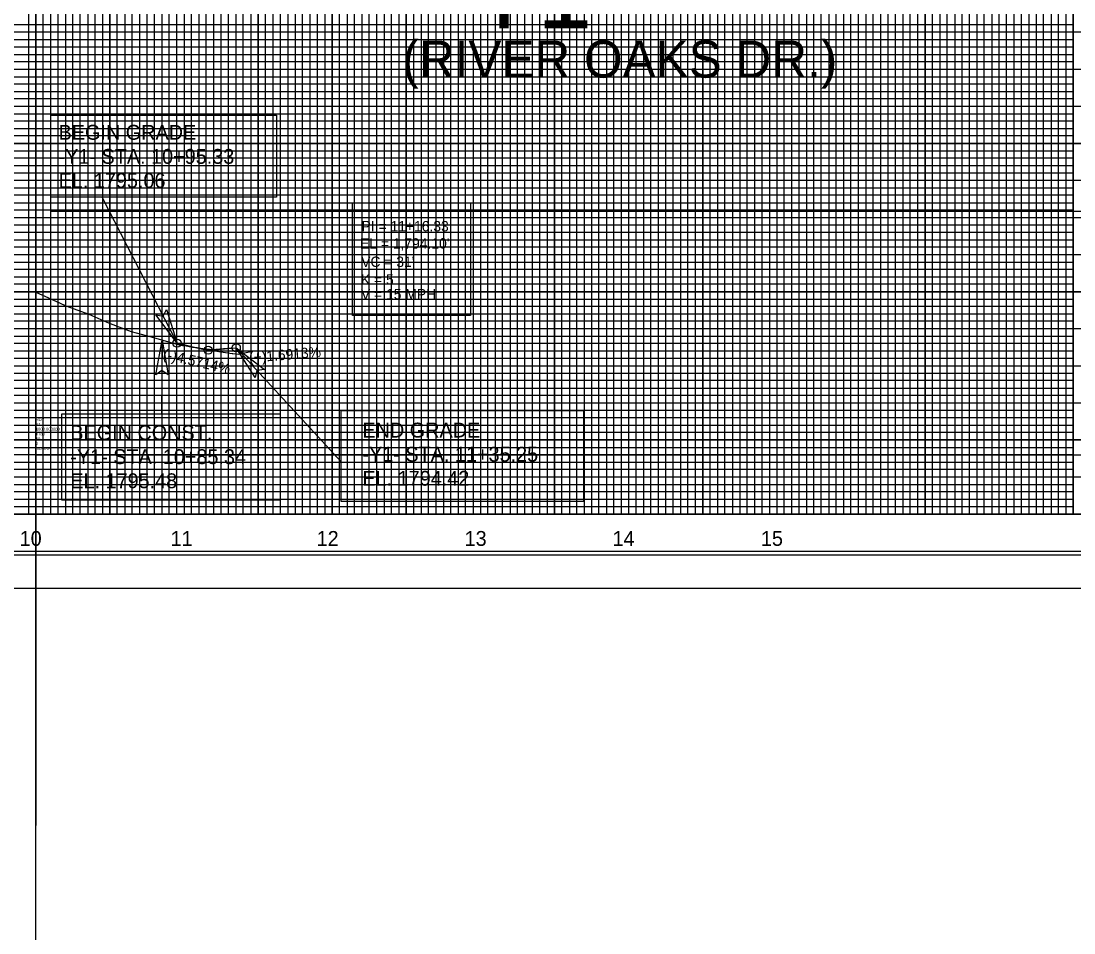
# Model space of a CAD drawing. Extents: x 572269 to 579912, y -56875 to -49627.
# Drawn here: x 574575 to 575285, y -54080 to -53465 of the extents above; entities that cross this region are included whole.
import ezdxf

# ---------------------------------------------------------------- set-up
doc = ezdxf.new("R2010")
doc.units = 0
for name, color, linetype in [('Exist Profile Cell', 7, 'Continuous'), ('Exist Vertical Profile Ground Line', 7, 'Continuous'), ('Exist Vertical Profile Horizontal Axis Label Major', 7, 'Continuous'), ('Prop Grid Mask', 7, 'Continuous'), ('Prop PFL Text', 7, 'Continuous'), ('Prop Vertical Profile Curve Label', 7, 'Continuous'), ('Prop Vertical Profile Grade', 7, 'Continuous'), ('Prop Vertical Profile Grade Label', 7, 'Continuous'), ('Prop VPI Label', 7, 'Continuous'), ('Scratch_Level_0', 7, 'Continuous'), ('Scratch_Level_3', 7, 'Continuous'), ('Scratch_Level_5', 7, 'Continuous'), ('Scratch_Level_6', 7, 'Continuous'), ('Sheet Cutting Line CELL', 7, 'Continuous'), ('Sheet DOT Grid CELL', 7, 'Continuous'), ('Sheet Layout Profile Border', 7, 'Continuous'), ('Sheet Plot Border Inside CELL', 7, 'Continuous'), ('Sheet Plot Border Outside CELL', 7, 'Continuous'), ('Sheet Profile CELL', 7, 'Continuous'), ('Sheet Profile Grid Major CELL', 7, 'Continuous'), ('Sheet Profile Grid Middle CELL', 7, 'Continuous'), ('Sheet Profile Grid Minor CELL', 7, 'Continuous'), ('Typical Terminator CELL', 7, 'Continuous')]:
    doc.layers.add(name, color=color, linetype=linetype)

# ---------------------------------------------------------------- blocks, each defined once
blk = doc.blocks.new('TERMINATOR')
at = {"layer": 'Typical Terminator CELL'}
blk.add_lwpolyline([(-0.469, 0.081), (0, 0), (-0.471, -0.083), (-0.411, 0)], close=True, dxfattribs=at)
blk = doc.blocks.new('PROFILE SHEET SINGLE')
at = {"layer": 'Sheet Cutting Line CELL'}
blk.add_line((-3.34, -0.5), (30.34, -0.5), dxfattribs=at)
at = {"layer": 'Sheet DOT Grid CELL'}
for p, q in [((15, 21), (15, 0.5)), ((16, 21), (16, 0.5)), ((17, 21), (17, 0.5)), ((18, 21), (18, 0.5)), ((19, 21), (19, 0.5)), ((20, 21), (20, 0.5)), ((21, 21), (21, 0.5)), ((22, 21), (22, 0.5)), ((23, 21), (23, 0.5)), ((24, 21), (24, 0.5)), ((25, 21), (25, 0.5)), ((26, 0.5), (26, 18.249)), ((27, 0.5), (27, 18.249)), ((28, 0.5), (28, 18.249)), ((29, 0.5), (29, 18.249)), ((0, 6.5), (30, 6.5)), ((0, 5.5), (30, 5.5)), ((0, 4.5), (30, 4.5)), ((0, 3.5), (30, 3.5)), ((0, 2.5), (30, 2.5)), ((0, 1.5), (30, 1.5))]:
    blk.add_line(p, q, dxfattribs=at)
at = {"layer": 'Sheet Plot Border Inside CELL'}
blk.add_lwpolyline([(30.25, 21.051), (-3.08, 21.051), (-3.08, -0.051), (30.25, -0.051)], close=True, dxfattribs=at)
at = {"layer": 'Sheet Plot Border Outside CELL'}
blk.add_lwpolyline([(30.34, 21.5), (-3.34, 21.5), (-3.34, -0.5), (30.34, -0.5)], close=True, dxfattribs=at)
at = {"layer": 'Sheet Profile CELL'}
blk.add_line((30, 0.5), (0, 0.5), dxfattribs=at)
blk.add_lwpolyline([(30, 21), (0, 21), (0, 0), (30, 0)], close=True, dxfattribs=at)
at = {"layer": 'Sheet Profile Grid Major CELL'}
for points in [[(15, 21), (15, 0.5), (16, 0.5), (16, 21)], [(17, 21), (17, 0.5), (18, 0.5), (18, 21)], [(19, 21), (19, 0.5), (20, 0.5), (20, 21)], [(21, 21), (21, 0.5), (22, 0.5), (22, 21)], [(23, 21), (23, 0.5), (24, 0.5), (24, 21)], [(25, 21), (25, 0.5), (26, 0.5), (26, 21)], [(27, 18.249), (27, 0.5), (28, 0.5), (28, 18.249)], [(29, 18.249), (29, 0.5), (30, 0.5)], [(30, 5.5), (0, 5.5), (0, 6.5), (30, 6.5)], [(30, 3.5), (0, 3.5), (0, 4.5), (30, 4.5)], [(30, 1.5), (0, 1.5), (0, 2.5), (30, 2.5)]]:
    blk.add_lwpolyline(points, dxfattribs=at)
at = {"layer": 'Sheet Profile Grid Middle CELL'}
for points in [[(14.5, 21), (14.5, 0.5), (15.5, 0.5), (15.5, 21)], [(16.5, 21), (16.5, 0.5), (17.5, 0.5), (17.5, 21)], [(18.5, 21), (18.5, 0.5), (19.5, 0.5), (19.5, 21)], [(20.5, 21), (20.5, 0.5), (21.5, 0.5), (21.5, 21)], [(22.5, 21), (22.5, 0.5), (23.5, 0.5), (23.5, 21)], [(24.5, 21), (24.5, 0.5), (25.5, 0.5), (25.5, 21)], [(26.5, 18.249), (26.5, 0.5), (27.5, 0.5), (27.5, 18.249)], [(28.5, 18.249), (28.5, 0.5)], [(30, 7), (0, 7), (0, 6), (30, 6)], [(30, 5), (0, 5), (0, 4), (30, 4)], [(30, 3), (0, 3), (0, 2), (30, 2)], [(30, 1), (0, 1)]]:
    blk.add_lwpolyline(points, dxfattribs=at)
at = {"layer": 'Sheet Profile Grid Minor CELL'}
for points in [[(14.9, 21), (14.9, 0.5), (15.1, 0.5), (15.1, 21)], [(15.2, 21), (15.2, 0.5)], [(15.2, 0.5), (15.3, 0.5), (15.3, 20.988)], [(15.4, 20.988), (15.4, 0.5), (15.6, 0.5), (15.6, 21)], [(15.7, 21), (15.7, 0.5), (15.8, 0.5), (15.8, 21)], [(15.9, 21), (15.9, 0.5), (16.1, 0.5), (16.1, 21)], [(16.2, 21), (16.2, 0.5), (16.3, 0.5), (16.3, 21)], [(16.4, 21), (16.4, 0.5), (16.6, 0.5), (16.6, 21)], [(16.7, 21), (16.7, 0.5), (16.8, 0.5), (16.8, 21)], [(16.9, 21), (16.9, 0.5), (17.1, 0.5), (17.1, 21)], [(17.2, 21), (17.2, 0.5), (17.3, 0.5), (17.3, 21)], [(17.4, 21), (17.4, 0.5), (17.6, 0.5), (17.6, 21)], [(17.7, 21), (17.7, 0.5), (17.8, 0.5), (17.8, 21)], [(17.9, 21), (17.9, 0.5), (18.1, 0.5), (18.1, 21)], [(18.2, 21), (18.2, 0.5), (18.3, 0.5), (18.3, 21)], [(18.4, 21), (18.4, 0.5), (18.6, 0.5), (18.6, 21)], [(18.7, 21), (18.7, 0.5), (18.8, 0.5), (18.8, 21)], [(18.9, 21), (18.9, 0.5), (19.1, 0.5), (19.1, 21)], [(19.2, 21), (19.2, 0.5), (19.3, 0.5), (19.3, 21)], [(19.4, 21), (19.4, 0.5), (19.6, 0.5), (19.6, 21)], [(19.7, 21), (19.7, 0.5), (19.8, 0.5), (19.8, 21)], [(19.9, 21), (19.9, 0.5), (20.1, 0.5), (20.1, 21)], [(20.2, 21), (20.2, 0.5), (20.3, 0.5), (20.3, 21)], [(20.4, 21), (20.4, 0.5), (20.6, 0.5), (20.6, 21)], [(20.7, 21), (20.7, 0.5), (20.8, 0.5), (20.8, 21)], [(20.9, 21), (20.9, 0.5), (21.1, 0.5), (21.1, 21)], [(21.2, 21), (21.2, 0.5), (21.3, 0.5), (21.3, 21)], [(21.4, 21), (21.4, 0.5)], [(21.4, 0.5), (21.6, 0.5), (21.6, 21)], [(21.7, 21), (21.7, 0.5), (21.8, 0.5), (21.8, 21)], [(21.9, 21), (21.9, 0.5), (22.1, 0.5), (22.1, 21)], [(22.2, 21), (22.2, 0.5), (22.3, 0.5), (22.3, 21)], [(22.4, 21), (22.4, 0.5), (22.6, 0.5), (22.6, 21)], [(22.7, 21), (22.7, 0.5), (22.8, 0.5), (22.8, 21)], [(22.9, 21), (22.9, 0.5), (23.1, 0.5), (23.1, 21)], [(23.2, 21), (23.2, 0.5), (23.3, 0.5), (23.3, 21)], [(23.4, 21), (23.4, 0.5), (23.6, 0.5), (23.6, 21)], [(23.7, 21), (23.7, 0.5), (23.8, 0.5), (23.8, 21)], [(23.9, 21), (23.9, 0.5), (24.1, 0.5), (24.1, 21)], [(24.2, 21), (24.2, 0.5), (24.3, 0.5), (24.3, 21)], [(24.4, 21), (24.4, 0.5), (24.6, 0.5), (24.6, 21)], [(24.7, 21), (24.7, 0.5), (24.8, 0.5), (24.8, 21)], [(24.9, 21), (24.9, 0.5), (25.1, 0.5), (25.1, 21)], [(25.2, 21), (25.2, 0.5), (25.3, 0.5), (25.3, 21)], [(25.4, 21), (25.4, 0.5), (25.6, 0.5), (25.6, 21)], [(25.7, 21), (25.7, 0.5), (25.8, 0.5), (25.8, 21)], [(25.9, 21), (25.9, 0.5), (26.1, 0.5), (26.1, 18.249)], [(26.2, 18.249), (26.2, 0.5), (26.3, 0.5), (26.3, 18.249)], [(26.4, 18.249), (26.4, 0.5), (26.6, 0.5), (26.6, 18.249)], [(26.7, 18.249), (26.7, 0.5), (26.8, 0.5), (26.8, 18.249)], [(26.9, 18.249), (26.9, 0.5), (27.1, 0.5), (27.1, 18.249)], [(27.2, 18.249), (27.2, 0.5), (27.3, 0.5), (27.3, 18.249)], [(27.4, 18.249), (27.4, 0.5), (27.6, 0.5), (27.6, 18.249)], [(27.7, 18.249), (27.7, 0.5)], [(27.7, 0.5), (27.8, 0.5), (27.8, 18.249)], [(27.9, 18.249), (27.9, 0.5), (28.1, 0.5), (28.1, 18.249)], [(28.2, 18.249), (28.2, 0.5), (28.3, 0.5), (28.3, 18.249)], [(28.4, 18.249), (28.4, 0.5), (28.6, 0.5), (28.6, 18.249)], [(28.7, 18.249), (28.7, 0.5), (28.8, 0.5), (28.8, 18.249)], [(28.9, 18.249), (28.9, 0.5), (29.1, 0.5)], [(29, 7.1), (1, 7.1), (1, 6.9), (29, 6.9)], [(29, 6.8), (1, 6.8), (1, 6.7), (29, 6.7)], [(29, 6.6), (1, 6.6), (1, 6.4), (29, 6.4)], [(29, 6.3), (1, 6.3), (1, 6.2), (29, 6.2)], [(29, 6.1), (1, 6.1), (1, 5.9), (29, 5.9)], [(29, 5.8), (1, 5.8), (1, 5.7), (29, 5.7)], [(29, 5.6), (1, 5.6), (1, 5.4), (29, 5.4)], [(29, 5.3), (1, 5.3), (1, 5.2), (29, 5.2)], [(29, 5.1), (1, 5.1), (1, 4.9), (29, 4.9)], [(29, 4.8), (1, 4.8), (1, 4.7), (29, 4.7)], [(29, 4.6), (1, 4.6)], [(1, 4.4), (29, 4.4)], [(29, 4.3), (1, 4.3), (1, 4.2), (29, 4.2)], [(29, 4.1), (1, 4.1)], [(1, 3.9), (29, 3.9)], [(29, 3.8), (1, 3.8), (1, 3.7), (29, 3.7)], [(29, 3.6), (1, 3.6), (1, 3.4), (29, 3.4)], [(29, 3.3), (1, 3.3), (1, 3.2), (29, 3.2)], [(29, 3.1), (1, 3.1), (1, 2.9), (29, 2.9)], [(29, 2.8), (1, 2.8), (1, 2.7), (29, 2.7)], [(29, 2.6), (1, 2.6), (1, 2.4), (29, 2.4)], [(29, 2.3), (1, 2.3), (1, 2.2), (29, 2.2)], [(29, 2.1), (1, 2.1), (1, 1.9), (29, 1.9)], [(29, 1.8), (1, 1.8), (1, 1.7), (29, 1.7)], [(29, 1.6), (1, 1.6), (1, 1.4), (29, 1.4)], [(29, 1.3), (1, 1.3), (1, 1.2), (29, 1.2)], [(29, 1.1), (1, 1.1), (1, 0.9), (29, 0.9)], [(29, 0.8), (1, 0.8), (1, 0.7), (29, 0.7)], [(29, 0.6), (1, 0.6)]]:
    blk.add_lwpolyline(points, dxfattribs=at)

msp = doc.modelspace()

# ---------------------------------------------------------------- linework, layer by layer
at = {"layer": 'Exist Profile Cell'}
for p, q in [((574584.69, -53347.71), (574584.69, -53597.71)), ((574584.69, -53757.71), (574584.69, -53507.71)), ((574584.69, -53757.71), (574730.02, -53757.71)), ((574584.69, -53757.71), (574584.69, -54007.71))]:
    msp.add_line(p, q, dxfattribs=at)
at = {"layer": 'Exist Vertical Profile Ground Line'}
msp.add_lwpolyline([(574584.69, -53648.13), (574593.15, -53651.84), (574604.1, -53656.84), (574604.67, -53657.04), (574605, -53657.16), (574620.5, -53662.83), (574632.57, -53668.34), (574640.73, -53671.39), (574649.01, -53674.48), (574662.56, -53678.26), (574674.24, -53681.49), (574680.76, -53683.32), (574681.67, -53683.5), (574683.73, -53683.91), (574686.09, -53684.27), (574688.09, -53684.69), (574690.47, -53685.04), (574692.42, -53685.46), (574694.49, -53685.76), (574696.35, -53686.18), (574717.22, -53689.31), (574717.63, -53689.39), (574721.14, -53689.89), (574728.95, -53688.3), (574730.02, -53688.06)], dxfattribs=at)
at = {"layer": 'Prop Grid Mask'}
for points in [[(574594.87, -53528.64), (574747.2, -53528.64), (574747.2, -53584.06), (574594.87, -53584.06)], [(574798.45, -53587.76), (574877.97, -53587.76), (574877.97, -53663.89), (574798.45, -53663.89)], [(574790.65, -53727.9), (574954.27, -53727.9), (574954.27, -53789.22), (574790.65, -53789.22)], [(574602.21, -53730.1), (574749.66, -53730.1), (574749.66, -53788.38), (574602.21, -53788.38)]]:
    msp.add_lwpolyline(points, close=True, dxfattribs=at)
at = {"layer": 'Prop PFL Text'}
for p, q in [((574680.02, -53682.41), (574629.57, -53584.06)), ((574670.03, -53680.31), (574669.52, -53730.1)), ((574719.94, -53685.61), (574790.65, -53762.55))]:
    msp.add_line(p, q, dxfattribs=at)
at = {"layer": 'Prop Vertical Profile Grade'}
for p, q in [((574680.02, -53682.41), (574692.51, -53685.26)), ((574680.02, -53682.41), (574685.52, -53683.67)), ((574709.52, -53686.49), (574719.94, -53685.61)), ((574716.52, -53685.9), (574719.94, -53685.61))]:
    msp.add_line(p, q, dxfattribs=at)
msp.add_spline([(574692.51, -53685.26), (574692.85, -53685.34), (574693.19, -53685.42), (574693.53, -53685.49), (574693.87, -53685.56), (574694.21, -53685.63), (574694.55, -53685.69), (574694.89, -53685.76), (574695.23, -53685.82), (574695.57, -53685.88), (574695.91, -53685.94), (574696.25, -53685.99), (574696.59, -53686.04), (574696.93, -53686.09), (574697.27, -53686.14), (574697.61, -53686.19), (574697.95, -53686.24), (574698.3, -53686.28), (574698.64, -53686.32), (574698.98, -53686.36), (574699.32, -53686.39), (574699.66, -53686.43), (574700, -53686.46), (574700.34, -53686.49), (574700.68, -53686.52), (574701.02, -53686.54), (574701.36, -53686.57), (574701.7, -53686.59), (574702.04, -53686.61), (574702.38, -53686.62), (574702.72, -53686.64), (574703.06, -53686.65), (574703.4, -53686.66), (574703.74, -53686.67), (574704.08, -53686.68), (574704.42, -53686.68), (574704.76, -53686.68), (574705.1, -53686.68), (574705.44, -53686.68), (574705.78, -53686.68), (574706.12, -53686.67), (574706.46, -53686.66), (574706.8, -53686.65), (574707.14, -53686.64), (574707.48, -53686.62), (574707.82, -53686.61), (574708.16, -53686.59), (574708.5, -53686.57), (574708.84, -53686.54), (574709.18, -53686.52), (574709.52, -53686.49)], degree=3, dxfattribs=at)
at = {"layer": 'Prop VPI Label'}
for p, q in [((574685.52, -53683.67), (574698.34, -53686.6)), ((574692.51, -53685.26), (574698.34, -53686.6)), ((574716.52, -53685.9), (574703.76, -53686.98)), ((574709.52, -53686.49), (574703.76, -53686.98))]:
    msp.add_line(p, q, dxfattribs=at)
for centre in [(574680.02, -53682.41), (574680.02, -53682.41), (574701.02, -53687.21), (574701.02, -53687.21), (574719.94, -53685.61), (574719.94, -53685.61)]:
    msp.add_circle(centre, 2.75, dxfattribs=at)
at = {"layer": 'Scratch_Level_0'}
msp.add_line((573884.69, -53497.71), (575215.07, -53497.71), dxfattribs=at)
at = {"layer": 'Scratch_Level_3'}
for p, q in [((574584.69, -56875.35), (574584.69, -49627.25)), ((574584.69, -53757.71), (575984.19, -53757.71))]:
    msp.add_line(p, q, dxfattribs=at)
at = {"layer": 'Scratch_Level_5'}
for p, q in [((574784.69, -53797.71), (574784.69, -52363.21)), ((574594.77, -53593.51), (575952.17, -53593.51)), ((574584.69, -53757.71), (576068.74, -53757.71))]:
    msp.add_line(p, q, dxfattribs=at)
at = {"layer": 'Scratch_Level_6'}
msp.add_line((574584.69, -54007.71), (574584.69, -52269.82), dxfattribs=at)
at = {"layer": 'Sheet Layout Profile Border'}
msp.add_lwpolyline([(573884.69, -52772.71), (573884.69, -53797.71), (575284.69, -53797.71), (575284.69, -52910.26), (575134.64, -52910.26), (575134.64, -52772.71)], close=True, dxfattribs=at)

# ---------------------------------------------------------------- block references
at = {"layer": 'Prop PFL Text'}
for p, xscale, yscale, rotation in [((574680.02, -53682.41), 50, 49.99999999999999, -62.883450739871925), ((574670.03, -53680.31), 49.99999999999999, 49.99999999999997, 89.42793698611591), ((574719.94, -53685.61), 50, 49.99999999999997, 132.4514251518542)]:
    msp.add_blockref('TERMINATOR', p, dxfattribs=dict(at, xscale=xscale, yscale=yscale, rotation=rotation))
at = {"layer": 'Sheet Cutting Line CELL', "xscale": 50, "yscale": 50}
msp.add_blockref('PROFILE SHEET SINGLE', (573834.69, -53822.71), dxfattribs=at)

# ---------------------------------------------------------------- texts
at = {"layer": 'Exist Profile Cell'}
for s, p in [('RDY', (574584.69, -53734.96)), ('Y1', (574584.69, -53738.21)), ('1000.000000', (574584.69, -53741.46)), ('2', (574584.69, -53751.21)), ('1780', (574584.69, -53744.71)), ('10', (574584.69, -53747.96)), ('NOGAP', (574584.69, -53754.46))]:
    msp.add_text(s, height=2, dxfattribs=at).set_placement(p)
at = {"layer": 'Exist Vertical Profile Horizontal Axis Label Major'}
for s, p in [('10', (574573.78, -53819.14)), ('11', (574675.62, -53819.14)), ('12', (574774.17, -53819.14)), ('13', (574874, -53819.14)), ('14', (574973.84, -53819.14)), ('15', (575073.94, -53819.14))]:
    msp.add_text(s, height=10, dxfattribs=at).set_placement(p)
at = {"layer": 'Prop PFL Text'}
for s, height, p in [('-Y1-', 50, (574856.05, -53470.07)), ('(RIVER OAKS DR.)', 25, (574832, -53503.37)), ('BEGIN GRADE ', 10, (574600.06, -53545.23)), ('-Y1- STA. 10+95.33', 10, (574600.06, -53561.48)), ('EL. 1795.06', 10, (574600.06, -53577.73)), ('BEGIN CONST. ', 10, (574607.95, -53747.74)), ('END GRADE ', 10, (574805.06, -53746.07)), ('-Y1- STA. 10+85.34 ', 10, (574607.95, -53763.99)), ('-Y1- STA. 11+35.25 ', 10, (574805.06, -53762.32)), ('EL. 1795.48', 10, (574607.95, -53780.24)), ('EL. 1794.42', 10, (574805.06, -53778.57))]:
    msp.add_text(s, height=height, dxfattribs=at).set_placement(p)
at = {"layer": 'Prop Vertical Profile Curve Label'}
for s, p in [('K = 5', (574804.09, -53642.99)), ('V = 15 MPH', (574804.09, -53652.88))]:
    msp.add_text(s, height=7, dxfattribs=at).set_placement(p)
at = {"layer": 'Prop Vertical Profile Grade Label'}
for s, rotation, p in [('(+)1.6913%', 4.83381, (574728.85, -53695.7)), ('(-)4.5714%', 347.125, (574669.97, -53692.98))]:
    msp.add_text(s, height=7, rotation=rotation, dxfattribs=at).set_placement(p)
at = {"layer": 'Prop VPI Label'}
for s, p in [('PI = 11+16.33', (574804.5, -53607.05)), ("EL = 1,794.10'", (574803.45, -53618.66)), ("VC = 31'", (574804.26, -53631.04))]:
    msp.add_text(s, height=7, dxfattribs=at).set_placement(p)

doc.saveas('drawing.dxf')
